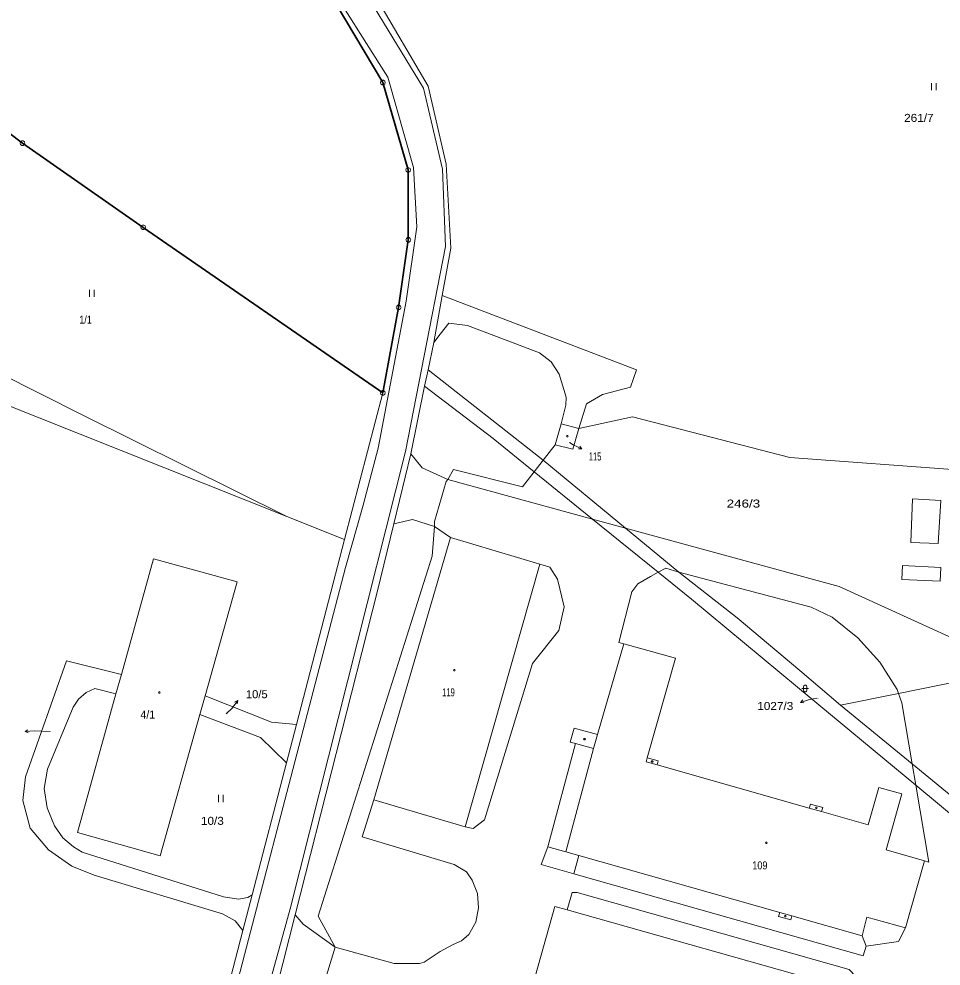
# Model space of a CAD drawing. Extents: x -687390 to -684106, y -954833 to -951648.
# Drawn here: x -686671.6 to -686475.8, y -952098.4 to -951897.2 of the extents above; entities that cross this region are included whole.
import ezdxf
from ezdxf.enums import TextEntityAlignment as Align

# ---------------------------------------------------------------- set-up
doc = ezdxf.new("R2010")
doc.units = 0
doc.header["$LTSCALE"] = 0.68
for name, color, linetype, lineweight in [('1', 7, 'Continuous', 13), ('3', 7, 'Continuous', 13), ('4', 7, 'Continuous', 13), ('5', 7, 'Continuous', 13), ('7', 7, 'Continuous', 13), ('8', 7, 'Continuous', 13)]:
    doc.layers.add(name, color=color, linetype=linetype, lineweight=lineweight)
doc.layers.add('2', color=7, linetype='Continuous')

msp = doc.modelspace()

# ---------------------------------------------------------------- linework, layer by layer
at = {"layer": '1'}
for p, q in [((-686584.66, -951911.47), (-686600.31, -951884.84)), ((-686579.91, -951945.87), (-686581.71, -951955.93)), ((-686581.71, -951955.93), (-686583.5, -951965.9)), ((-686704.16, -951958.27), (-686657.92, -951981.4)), ((-686583.5, -951965.9), (-686584.7, -951971.72)), ((-686699.9, -951969), (-686614.7, -952002.92)), ((-686584.7, -951971.72), (-686560.24, -951990.9)), ((-686585.44, -951975.23), (-686588.41, -951989.55)), ((-686602.46, -952007.79), (-686594.32, -951976.62)), ((-686614.7, -952002.92), (-686657.92, -951981.4)), ((-686570.92, -951986.31), (-686562.18, -951993.4)), ((-686588.41, -951989.55), (-686592, -952004.43)), ((-686542.79, -952005.36), (-686560.24, -951990.9)), ((-686562.18, -951993.4), (-686549.76, -952003.45)), ((-686614.7, -952002.92), (-686602.46, -952007.79)), ((-686549.76, -952003.45), (-686535.81, -952014.74)), ((-686592, -952004.43), (-686595.51, -952018.97)), ((-686531.48, -952014.73), (-686542.79, -952005.36)), ((-686602.46, -952007.79), (-686612.68, -952047.1)), ((-686535.81, -952014.74), (-686528.77, -952020.46)), ((-686531.48, -952014.73), (-686519.03, -952024.45)), ((-686625.28, -952016.78), (-686632.04, -952040.98)), ((-686612.96, -952087.48), (-686595.51, -952018.97)), ((-686506.22, -952039.16), (-686528.77, -952020.46)), ((-686505.72, -952035.58), (-686519.03, -952024.45)), ((-686543.13, -952029.92), (-686532.15, -952032.97)), ((-686649.86, -952036.45), (-686661.54, -952033.54)), ((-686532.15, -952032.97), (-686538.17, -952054.13)), ((-686497.1, -952042.99), (-686505.72, -952035.58)), ((-686649.86, -952036.45), (-686651, -952040.55)), ((-686651, -952040.55), (-686655.5, -952039.45)), ((-686481.13, -952059.97), (-686506.22, -952039.16)), ((-686651, -952040.55), (-686659.17, -952070.05)), ((-686632.04, -952040.98), (-686633.21, -952044.94)), ((-686497.1, -952042.99), (-686484.77, -952040.5)), ((-686497.1, -952042.99), (-686481.9, -952055.46)), ((-686641.6, -952074.98), (-686633.21, -952044.94)), ((-686620.33, -952049.83), (-686633.21, -952044.94)), ((-686559.29, -952073.06), (-686553.38, -952051.14)), ((-686554.5, -952050.84), (-686553.38, -952051.14)), ((-686535.81, -952054.8), (-686538.17, -952054.13)), ((-686614.8, -952055.23), (-686622.1, -952083.25)), ((-686535.81, -952054.8), (-686536.07, -952055.66)), ((-686503.74, -952064.84), (-686536.07, -952055.66)), ((-686461.34, -952072.38), (-686481.9, -952055.46)), ((-686659.17, -952070.05), (-686641.6, -952074.98)), ((-686559.29, -952073.06), (-686555.48, -952074.14)), ((-686555.48, -952074.14), (-686552.67, -952074.93)), ((-686552.67, -952074.93), (-686510.02, -952086.98)), ((-686622.1, -952083.25), (-686624.07, -952090.85)), ((-686622.1, -952083.25), (-686623.01, -952083.81)), ((-686563.98, -952107.85), (-686557.76, -952085.75)), ((-686557.76, -952085.75), (-686555.17, -952086.48)), ((-686617.95, -952107.08), (-686612.96, -952087.48)), ((-686555.17, -952086.48), (-686495.19, -952103.37)), ((-686624.07, -952090.85), (-686634.75, -952131.94))]:
    msp.add_line(p, q, dxfattribs=at)
at = {"layer": '1', "lineweight": 35}
msp.add_line((-686594.32, -951976.62), (-686645.21, -951941.46), dxfattribs=at)
for points in [[(-686594.32, -951976.62), (-686590.96, -951958.48), (-686588.91, -951944.13), (-686588.95, -951929.27), (-686594.33, -951910.7), (-686613.91, -951877.7), (-686619.82, -951861.59), (-686627.49, -951834.72), (-686634.07, -951817.98), (-686638.58, -951806.76), (-686653.33, -951789.49), (-686664.98, -951778.04), (-686686.92, -951758.42), (-686712.35, -951737.12), (-686729.49, -951726.58)], [(-686687.49, -951911.03), (-686670.84, -951923.59), (-686645.21, -951941.46)]]:
    msp.add_lwpolyline(points, dxfattribs=at)
at = {"layer": '1'}
for points in [[(-686584.66, -951911.47), (-686580.87, -951928.07), (-686579.91, -951945.87)], [(-686432.68, -952023.41), (-686463.81, -952009.3), (-686471.42, -951993.03), (-686507.87, -951990.35), (-686541.31, -951981.69), (-686552.72, -951984.21), (-686551.08, -951978.97), (-686547.66, -951976.98), (-686541.72, -951975.44), (-686540.46, -951971.73), (-686581.71, -951955.93)], [(-686584.7, -951971.72), (-686585.44, -951975.23), (-686570.92, -951986.31)], [(-686625.28, -952016.78), (-686643.04, -952011.87), (-686649.86, -952036.45)], [(-686554.5, -952050.84), (-686553.67, -952047.86), (-686548.72, -952049.23), (-686543.13, -952029.92)], [(-686484.77, -952040.5), (-686475.71, -952038.67), (-686438.18, -952031.13)], [(-686661.54, -952033.54), (-686670.19, -952058.18), (-686670.76, -952063.23), (-686669.19, -952069.07), (-686665.35, -952073.7), (-686660.37, -952077.18), (-686655.64, -952079.06), (-686628.4, -952087.32), (-686625.7, -952088.8), (-686624.07, -952090.85)], [(-686623.01, -952083.81), (-686625.01, -952084.17), (-686628.13, -952083.65), (-686658.2, -952074.21), (-686660, -952073.09), (-686662.29, -952071.18), (-686664.07, -952068.62), (-686665.63, -952064.76), (-686666.25, -952060.69), (-686665.53, -952056.53), (-686660.11, -952043.41), (-686658.99, -952041.72), (-686657.35, -952040.26), (-686655.5, -952039.45)], [(-686632.04, -952040.98), (-686617.99, -952046.56), (-686612.68, -952047.1)], [(-686612.68, -952047.1), (-686614.8, -952055.23), (-686620.33, -952049.83)], [(-686481.13, -952059.97), (-686462.31, -952075.62), (-686461.21, -952076.54)], [(-686484.1, -952061.83), (-686487.45, -952073.72), (-686479.28, -952076.02), (-686483.28, -952090.3), (-686491.49, -952087.97), (-686492.5, -952091.95), (-686507.42, -952087.71), (-686507.67, -952088.58), (-686510.26, -952087.84), (-686510.02, -952086.98)], [(-686484.1, -952061.83), (-686489.01, -952060.47), (-686491.24, -952068.38)], [(-686503.74, -952064.84), (-686503.49, -952063.98), (-686500.89, -952064.71), (-686501.14, -952065.58), (-686491.24, -952068.38)]]:
    msp.add_lwpolyline(points, dxfattribs=at)
for points in [[(-686556.46, -951983.18), (-686557.71, -951987.63), (-686553.94, -951988.61), (-686552.72, -951984.21)], [(-686579.92, -952007.37), (-686596.26, -952063.09), (-686576.82, -952068.8), (-686560.96, -952013.04)]]:
    msp.add_lwpolyline(points, close=True, dxfattribs=at)
at = {"layer": '3'}
for p, q in [((-686477.77, -951910.82), (-686477.77, -951912.32)), ((-686476.77, -951912.32), (-686476.77, -951910.82)), ((-686656.61, -951954.71), (-686656.61, -951956.21)), ((-686655.61, -951956.21), (-686655.61, -951954.71)), ((-686629.25, -952062.05), (-686629.25, -952063.55)), ((-686628.25, -952063.55), (-686628.25, -952062.05))]:
    msp.add_line(p, q, dxfattribs=at)
msp.add_lwpolyline([(-686505.33, -952039.45), (-686504.416, -952039.45), (-686503.89, -952039.45)], dxfattribs=at)
msp.add_lwpolyline([(-686504.97, -952039.09), (-686504.898, -952038.881), (-686504.718, -952038.752), (-686504.495, -952038.752), (-686504.315, -952038.881), (-686504.243, -952039.09), (-686504.243, -952039.81), (-686504.315, -952040.019), (-686504.495, -952040.148), (-686504.718, -952040.148), (-686504.898, -952040.019), (-686504.97, -952039.81)], close=True, dxfattribs=at)
at = {"layer": '4'}
for p, q in [((-686589.38, -951957.11), (-686595.31, -951988.34)), ((-686580.33, -951961.85), (-686582.15, -951964.17)), ((-686583.5, -951965.9), (-686582.15, -951964.17)), ((-686557.71, -951987.63), (-686560.24, -951990.9)), ((-686589.51, -951989.05), (-686613.98, -952086.25)), ((-686598.47, -952000.5), (-686595.31, -951988.34)), ((-686560.24, -951990.9), (-686562.18, -951993.4)), ((-686562.18, -951993.4), (-686564.69, -951996.62)), ((-686549.76, -952003.45), (-686580.5, -951995.03)), ((-686475.83, -951999.47), (-686476.38, -952008.59)), ((-686598.47, -952000.5), (-686602.22, -952013.72)), ((-686592, -952004.43), (-686588.04, -952003.52)), ((-686588.04, -952003.52), (-686583.34, -952004.98)), ((-686542.79, -952005.36), (-686549.76, -952003.45)), ((-686497.43, -952017.79), (-686542.79, -952005.36)), ((-686535.81, -952014.74), (-686534.21, -952013.88)), ((-686483.97, -952013.27), (-686475.78, -952013.69)), ((-686497.43, -952017.79), (-686473.35, -952028.72)), ((-686484.11, -952042.49), (-686481.9, -952055.46)), ((-686549.56, -952052.19), (-686548.72, -952049.23)), ((-686555.48, -952074.14), (-686549.56, -952052.19)), ((-686549.56, -952052.19), (-686553.38, -952051.14)), ((-686538.42, -952054.99), (-686538.17, -952054.13)), ((-686538.42, -952054.99), (-686536.07, -952055.66)), ((-686481.9, -952055.46), (-686481.13, -952059.97)), ((-686481.13, -952059.97), (-686478.36, -952076.29)), ((-686503.74, -952064.84), (-686501.14, -952065.58)), ((-686553.77, -952078.82), (-686552.67, -952074.93)), ((-686478.36, -952076.29), (-686479.28, -952076.02)), ((-686555.17, -952086.48), (-686554.1, -952082.73)), ((-686630.91, -952147.24), (-686613.98, -952086.25)), ((-686510.02, -952086.98), (-686507.42, -952087.71)), ((-686604.48, -952094.39), (-686606.29, -952100.39))]:
    msp.add_line(p, q, dxfattribs=at)
for points in [[(-686589.51, -951989.05), (-686581.03, -951945.55), (-686581.65, -951929.09), (-686585.67, -951911.88), (-686601.7, -951885.53), (-686611.71, -951863.35), (-686618.41, -951839.13), (-686630.8, -951807.13), (-686622.42, -951763.23), (-686614.3, -951734.72)], [(-686589.38, -951957.11), (-686587.12, -951941.32), (-686587.84, -951928.76), (-686593.29, -951909.56), (-686603.16, -951893.91), (-686612.74, -951876.89), (-686619.28, -951860.27)], [(-686580.33, -951961.85), (-686576.36, -951962.28), (-686561.02, -951968.09), (-686558.57, -951970.06), (-686556.9, -951972.67), (-686555.35, -951977.52), (-686555.48, -951979.24), (-686556.46, -951983.18)], [(-686580.5, -951995.03), (-686585.98, -951992.58), (-686588.41, -951989.55)], [(-686564.69, -951996.62), (-686579.31, -951992.9), (-686580.5, -951995.03), (-686580.88, -951995.47), (-686583.34, -952003.95), (-686583.34, -952004.98), (-686579.92, -952007.37)], [(-686475.83, -951999.47), (-686481.84, -951999.14), (-686482.18, -952008.38), (-686476.38, -952008.59)], [(-686583.34, -952004.98), (-686583.82, -952011.33), (-686608.09, -952087.82), (-686604.48, -952094.39), (-686611.27, -952089.5), (-686612.96, -952087.48)], [(-686634.75, -952131.94), (-686633.22, -952132.4), (-686602.22, -952013.72)], [(-686560.96, -952013.04), (-686558.82, -952013.67), (-686557.23, -952016.2), (-686555.8, -952022.11), (-686556.94, -952027.11), (-686562.5, -952034.11), (-686572.76, -952067.33), (-686575.11, -952069.18), (-686576.82, -952068.8)], [(-686534.21, -952013.88), (-686531.48, -952014.73), (-686503.38, -952022.18), (-686498.87, -952024.3), (-686493.46, -952028.69), (-686488.75, -952033.8), (-686485.05, -952039.67)], [(-686483.97, -952013.27), (-686484.12, -952016.26), (-686475.92, -952016.65), (-686475.78, -952013.69)], [(-686543.13, -952029.92), (-686544.21, -952029.62), (-686541.42, -952018.9), (-686540.14, -952017.19), (-686537.5, -952015.65), (-686535.81, -952014.74)], [(-686485.05, -952039.67), (-686484.77, -952040.5), (-686484.11, -952042.49)], [(-686604.48, -952094.39), (-686591.89, -952097.84), (-686586.54, -952097.86), (-686585.56, -952097.54), (-686582.16, -952095.32), (-686579.35, -952093.79), (-686577.63, -952093.04), (-686576.08, -952091.72), (-686574.59, -952089.06), (-686573.98, -952086.01), (-686574.22, -952082.98), (-686575.34, -952080.12), (-686576.54, -952078.35), (-686579.2, -952076.8), (-686598.68, -952070.96), (-686596.26, -952063.09)], [(-686491.69, -952094.14), (-686492.28, -952096.23), (-686553.77, -952078.82), (-686560.72, -952076.83), (-686559.29, -952073.06)], [(-686494.39, -952103.57), (-686493.89, -952100.6), (-686495.3, -952099.13), (-686553.02, -952082.78), (-686554.1, -952082.73)], [(-686483.28, -952090.3), (-686484.78, -952093.2), (-686491.69, -952094.14), (-686492.5, -952091.95)]]:
    msp.add_lwpolyline(points, dxfattribs=at)
at = {"layer": '5'}
for points in [[(-686555.06, -951985.68), (-686554.97, -951985.83), (-686555.06, -951985.98), (-686555.24, -951985.98), (-686555.33, -951985.83), (-686555.24, -951985.68)], [(-686579.04, -952035.36), (-686578.95, -952035.51), (-686579.04, -952035.66), (-686579.22, -952035.66), (-686579.31, -952035.51), (-686579.22, -952035.36)], [(-686641.72, -952040.12), (-686641.63, -952040.27), (-686641.72, -952040.42), (-686641.9, -952040.42), (-686641.99, -952040.27), (-686641.9, -952040.12)], [(-686551.4, -952050.04), (-686551.31, -952050.19), (-686551.4, -952050.34), (-686551.58, -952050.34), (-686551.67, -952050.19), (-686551.58, -952050.04)], [(-686537.03, -952054.78), (-686536.94, -952054.93), (-686537.03, -952055.08), (-686537.21, -952055.08), (-686537.3, -952054.93), (-686537.21, -952054.78)], [(-686502.17, -952064.63), (-686502.08, -952064.78), (-686502.17, -952064.93), (-686502.35, -952064.93), (-686502.44, -952064.78), (-686502.35, -952064.63)], [(-686512.81, -952072.05), (-686512.72, -952072.2), (-686512.81, -952072.35), (-686512.99, -952072.35), (-686513.08, -952072.2), (-686512.99, -952072.05)], [(-686508.73, -952087.64), (-686508.64, -952087.79), (-686508.73, -952087.94), (-686508.91, -952087.94), (-686509, -952087.79), (-686508.91, -952087.64)]]:
    msp.add_lwpolyline(points, close=True, dxfattribs=at)
at = {"layer": '7'}
for p, q in [((-686554.65, -951987.17), (-686553.87, -951987.67)), ((-686552.043, -951988.509), (-686553.87, -951987.67)), ((-686625.128, -952041.984), (-686626.35, -952043.58)), ((-686505.629, -952042.389), (-686503.72, -952041.76)), ((-686502.17, -952041.49), (-686503.72, -952041.76)), ((-686627.58, -952044.79), (-686626.35, -952043.58)), ((-686670.321, -952048.589), (-686668.32, -952048.4)), ((-686664.97, -952048.55), (-686668.32, -952048.4))]:
    msp.add_line(p, q, dxfattribs=at)
for points in [[(-686552.512, -951987.925), (-686552.043, -951988.509), (-686552.792, -951988.534)], [(-686625.802, -952042.312), (-686625.128, -952041.984), (-686625.27, -952042.719)], [(-686504.888, -952042.497), (-686505.629, -952042.389), (-686505.098, -952041.861)], [(-686669.623, -952048.86), (-686670.321, -952048.589), (-686669.686, -952048.193)]]:
    msp.add_lwpolyline(points, dxfattribs=at)
at = {"layer": '8'}
for p, q in [((-686594.45, -951910.7), (-686594.21, -951910.7)), ((-686670.96, -951923.59), (-686670.72, -951923.59)), ((-686589.07, -951929.27), (-686588.83, -951929.27)), ((-686645.33, -951941.46), (-686645.09, -951941.46)), ((-686589.03, -951944.13), (-686588.79, -951944.13)), ((-686591.08, -951958.48), (-686590.84, -951958.48)), ((-686594.44, -951976.62), (-686594.2, -951976.62))]:
    msp.add_line(p, q, dxfattribs=at)
for points in [[(-686594.18, -951910.22), (-686593.93, -951910.4), (-686593.83, -951910.69), (-686593.93, -951910.98), (-686594.18, -951911.16), (-686594.49, -951911.16), (-686594.74, -951910.98), (-686594.84, -951910.69), (-686594.74, -951910.4), (-686594.49, -951910.22)], [(-686670.69, -951923.11), (-686670.44, -951923.29), (-686670.34, -951923.58), (-686670.44, -951923.87), (-686670.69, -951924.05), (-686671, -951924.05), (-686671.25, -951923.87), (-686671.35, -951923.58), (-686671.25, -951923.29), (-686671, -951923.11)], [(-686588.8, -951928.79), (-686588.55, -951928.97), (-686588.45, -951929.26), (-686588.55, -951929.55), (-686588.8, -951929.73), (-686589.11, -951929.73), (-686589.36, -951929.55), (-686589.46, -951929.26), (-686589.36, -951928.97), (-686589.11, -951928.79)], [(-686645.06, -951940.98), (-686644.81, -951941.16), (-686644.71, -951941.45), (-686644.81, -951941.74), (-686645.06, -951941.92), (-686645.37, -951941.92), (-686645.62, -951941.74), (-686645.72, -951941.45), (-686645.62, -951941.16), (-686645.37, -951940.98)], [(-686588.76, -951943.65), (-686588.51, -951943.83), (-686588.41, -951944.12), (-686588.51, -951944.41), (-686588.76, -951944.59), (-686589.07, -951944.59), (-686589.32, -951944.41), (-686589.42, -951944.12), (-686589.32, -951943.83), (-686589.07, -951943.65)], [(-686590.81, -951958), (-686590.56, -951958.18), (-686590.46, -951958.47), (-686590.56, -951958.76), (-686590.81, -951958.94), (-686591.12, -951958.94), (-686591.37, -951958.76), (-686591.47, -951958.47), (-686591.37, -951958.18), (-686591.12, -951958)], [(-686594.17, -951976.14), (-686593.92, -951976.32), (-686593.82, -951976.61), (-686593.92, -951976.9), (-686594.17, -951977.08), (-686594.48, -951977.08), (-686594.73, -951976.9), (-686594.83, -951976.61), (-686594.73, -951976.32), (-686594.48, -951976.14)]]:
    msp.add_lwpolyline(points, close=True, dxfattribs=at)

# ---------------------------------------------------------------- texts
at = {"layer": '2'}
for s, height, width, p in [('261/7', 1.7, 1.1, (-686483.605, -951919.06)), ('1/1', 1.7, 0.85, (-686658.805, -951961.93)), ('115', 0.1, 0.7, (-686554.604, -951987.17)), ('246/3', 1.7, 1.25, (-686521.295, -952000.99)), ('119', 1.7, 0.65, (-686581.715, -952041.08)), ('1027/3', 0.1, 1.1, (-686502.124, -952041.49)), ('10/5', 0.1, 1.05, (-686627.534, -952044.79)), ('10/4', 0.1, 1.05, (-686664.924, -952048.55)), ('10/3', 1.7, 1.1, (-686632.965, -952068.39)), ('109', 1.7, 0.85, (-686515.855, -952077.85))]:
    msp.add_text(s, height=height, dxfattribs=dict(at, width=width)).set_placement(p)
msp.add_text('4/1', height=1.7, dxfattribs=at).set_placement((-686645.825, -952045.82))
at = {"layer": '7'}
for s, width, p in [('115', 0.7, (-686550.565, -951990.99)), ('10/5', 1.05, (-686623.425, -952041.49))]:
    msp.add_text(s, height=1.7, dxfattribs=dict(at, width=width)).set_placement(p)
at = {"layer": '7', "width": 1.1}
msp.add_text('1027/3', height=1.7, dxfattribs=at).set_placement((-686507.146, -952043.99), align=Align.RIGHT)

doc.saveas('drawing.dxf')
